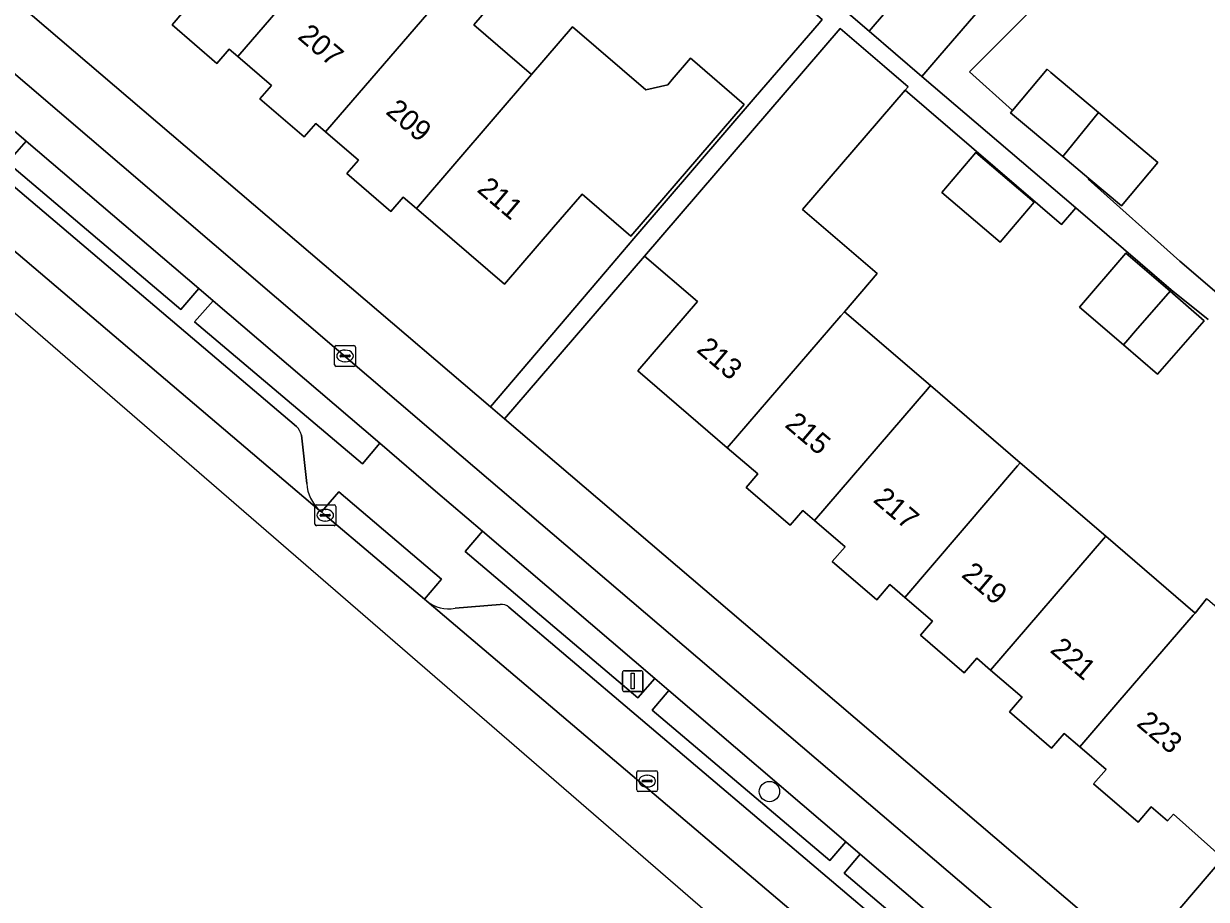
# Model space of a CAD drawing. Extents: x 162523 to 163266, y 381230 to 382050.
# Drawn here: x 162580.1 to 162636.9, y 381740.5 to 381782.6 of the extents above; entities that cross this region are included whole.
import ezdxf

# ---------------------------------------------------------------- set-up
doc = ezdxf.new("R2010")
doc.units = 0
for name, color, linetype in [('IMGEO_Berm_groen', 7, 'Continuous'), ('IMGEO_Berm_open', 7, 'Continuous'), ('IMGEO_Boom', 7, 'Continuous'), ('IMGEO_Brandkraan', 7, 'Continuous'), ('IMGEO_Erf', 7, 'Continuous'), ('IMGEO_Fietspad_gesloten', 7, 'Continuous'), ('IMGEO_Kolk', 7, 'Continuous'), ('IMGEO_Lichtmast', 7, 'Continuous'), ('IMGEO_Pand', 7, 'Continuous'), ('IMGEO_Pand_nummerreeks', 7, 'Continuous'), ('IMGEO_Parkeervlak_open', 7, 'Continuous'), ('IMGEO_Rijbaan_lokaal_gesloten', 7, 'Continuous'), ('IMGEO_Voetpad_open', 7, 'Continuous')]:
    doc.layers.add(name, color=color, linetype=linetype)

msp = doc.modelspace()

# ---------------------------------------------------------------- linework, layer by layer
at = {"layer": 'IMGEO_Berm_groen'}
for points in [[(162580.204, 381776.991), (162579.301, 381775.955), (162587.628, 381768.898), (162588.493, 381769.903)], [(162589.179, 381769.316), (162588.292, 381768.298), (162596.362, 381761.478), (162597.187, 381762.468)], [(162602.123, 381758.248), (162601.292, 381757.262), (162609.598, 381750.237), (162610.407, 381751.166)], [(162611.084, 381750.587), (162610.29, 381749.64), (162618.823, 381742.409), (162619.592, 381743.314)], [(162620.285, 381742.721), (162619.506, 381741.806), (162627.912, 381734.688), (162628.68, 381735.544)]]:
    msp.add_lwpolyline(points, close=True, dxfattribs=at)
at = {"layer": 'IMGEO_Berm_open'}
for points in [[(162572.745, 381780.619), (162593.185, 381763.279)], [(162627.912, 381734.688), (162619.506, 381741.806), (162620.285, 381742.721), (162619.592, 381743.314), (162618.823, 381742.409), (162610.29, 381749.64), (162611.084, 381750.587), (162610.407, 381751.166), (162609.598, 381750.237), (162601.292, 381757.262), (162602.123, 381758.248), (162599.877, 381760.168), (162597.187, 381762.468), (162596.362, 381761.478), (162588.292, 381768.298), (162589.179, 381769.316), (162588.493, 381769.903), (162587.628, 381768.898), (162579.301, 381775.955), (162580.204, 381776.991), (162579.513, 381777.583)], [(162593.426, 381762.861), (162593.683, 381760.532)], [(162594.297, 381759.242), (162594.384, 381759.168), (162595.221, 381760.134), (162600.155, 381755.935), (162599.342, 381754.973), (162599.458, 381754.875)], [(162600.809, 381754.538), (162602.985, 381754.717)], [(162603.395, 381754.59), (162624.819, 381736.42)]]:
    msp.add_lwpolyline(points, dxfattribs=at)
for centre, radius, start, end in [((162592.627, 381762.679), 0.819, 12.8339, 47.0977), ((162595.587, 381760.647), 1.907, 183.454, 227.452), ((162600.495, 381756.154), 1.646, 230.9738, 281.0135), ((162603.061, 381754.236), 0.487, 46.6334, 98.9453)]:
    msp.add_arc(centre, radius, start, end, dxfattribs=at)
at = {"layer": 'IMGEO_Boom'}
msp.add_circle((162615.919, 381745.727), 0.489, dxfattribs=at)
at = {"layer": 'IMGEO_Brandkraan'}
for p, q in [((162595.022, 381766.238), (162595.022, 381767.09)), ((162595.097, 381767.164), (162595.949, 381767.164)), ((162595.51, 381766.944), (162595.535, 381766.944)), ((162596.023, 381767.09), (162596.023, 381766.238)), ((162595.281, 381766.658), (162595.281, 381766.67)), ((162595.719, 381766.621), (162595.321, 381766.621)), ((162595.324, 381766.707), (162595.722, 381766.707)), ((162595.533, 381766.384), (162595.508, 381766.384)), ((162595.765, 381766.67), (162595.765, 381766.658)), ((162595.949, 381766.164), (162595.097, 381766.164))]:
    msp.add_line(p, q, dxfattribs=at)
for points in [[(162595.022, 381766.238), (162595.022, 381767.09)], [(162595.097, 381767.164), (162595.949, 381767.164)], [(162596.023, 381767.09), (162596.023, 381766.238)], [(162595.949, 381766.164), (162595.097, 381766.164)]]:
    msp.add_lwpolyline(points, dxfattribs=at)
for centre, radius, start, end in [((162595.099, 381767.088), 0.0765, 91.552, 178.448), ((162595.099, 381767.088), 0.0765, 91.552, 178.448), ((162595.947, 381767.088), 0.0765, 1.552, 88.448), ((162595.947, 381767.088), 0.0765, 1.552, 88.448), ((162595.099, 381766.24), 0.0765, 181.552, 268.448), ((162595.099, 381766.24), 0.0765, 181.552, 268.448), ((162595.321, 381766.667), 0.0403, 85.8775, 175.7526), ((162595.318, 381766.657), 0.0366, 178.938, 274.7102), ((162595.722, 381766.664), 0.043, 264.8664, 352.4533), ((162595.726, 381766.669), 0.0386, 1.7309, 96.639), ((162595.947, 381766.24), 0.0765, 271.552, 358.448), ((162595.947, 381766.24), 0.0765, 271.552, 358.448)]:
    msp.add_arc(centre, radius, start, end, dxfattribs=at)
for centre, major_axis, ratio, start_param, end_param in [((162595.509, 381766.664), (-0.387, 0.002), 0.722429, 4.712389, 7.853982), ((162595.534, 381766.664), (-0.39, 0.002), 0.717154, 1.570796, 4.712389)]:
    msp.add_ellipse(centre, major_axis=major_axis, ratio=ratio, start_param=start_param, end_param=end_param, dxfattribs=at)
at = {"layer": 'IMGEO_Erf'}
for points in [[(162549.054, 381809.864), (162602.511, 381764.218), (162608.044, 381770.714), (162609.399, 381772.305), (162615.239, 381779.1), (162618.303, 381782.666), (162618.448, 381782.836), (162612.38, 381788.011), (162610.349, 381789.742), (162611.057, 381790.567), (162610.568, 381790.987), (162608.033, 381793.165), (162605.498, 381795.343), (162602.964, 381797.522), (162600.429, 381799.7), (162597.894, 381801.878), (162595.359, 381804.056), (162592.824, 381806.234), (162590.289, 381808.413), (162588.022, 381810.361), (162584.229, 381805.946), (162580.559, 381801.594), (162578.078, 381803.689)], [(162603.937, 381785.179), (162601.706, 381782.58), (162604.485, 381780.192), (162606.452, 381782.481), (162609.976, 381779.451), (162611.034, 381779.701), (162611.251, 381779.954), (162612.126, 381780.973), (162612.218, 381780.894), (162614.705, 381778.757), (162609.262, 381772.423), (162606.912, 381774.443), (162605.543, 381772.85), (162603.19, 381770.112), (162598.952, 381773.754), (162598.317, 381774.3), (162597.722, 381773.608), (162595.606, 381775.427), (162596.163, 381776.075), (162594.587, 381777.43), (162594.114, 381777.836), (162593.561, 381777.193), (162591.426, 381779.027), (162591.98, 381779.671), (162590.368, 381781.056), (162589.951, 381781.415), (162589.36, 381780.727), (162587.209, 381782.576), (162587.78, 381783.24)], [(162628.845, 381783.631), (162625.54, 381780.326), (162627.603, 381778.469), (162629.26, 381780.442), (162629.439, 381780.292), (162631.729, 381778.368), (162634.592, 381775.963), (162632.84, 381773.877), (162631.275, 381775.192), (162631.242, 381775.155), (162635.646, 381771.227), (162638.212, 381769.032)], [(162636.996, 381768.418), (162635.231, 381769.841), (162630.643, 381773.79), (162629.953, 381772.98), (162622.441, 381779.445), (162617.514, 381773.709), (162621.101, 381770.629), (162619.522, 381768.791), (162623.657, 381765.237), (162627.976, 381761.526), (162632.08, 381758), (162636.378, 381754.306), (162636.928, 381754.989)]]:
    msp.add_lwpolyline(points, dxfattribs=at)
for points in [[(162624.198, 381774.516), (162625.84, 381776.446), (162628.643, 381774.06), (162627.001, 381772.13)], [(162623.171, 381753.249), (162623.75, 381753.923), (162622.427, 381755.06), (162621.709, 381755.677), (162621.077, 381754.942), (162618.936, 381756.782), (162619.55, 381757.497), (162618.078, 381758.762), (162617.524, 381759.238), (162616.913, 381758.528), (162614.803, 381760.341), (162615.361, 381760.991), (162613.893, 381762.252), (162609.593, 381765.948), (162612.46, 381769.285), (162609.92, 381771.468), (162603.191, 381763.638), (162619.163, 381750), (162633.579, 381737.69), (162637.705, 381742.522), (162635.34, 381744.646), (162635.056, 381744.315), (162634.271, 381744.989), (162633.638, 381744.253), (162631.499, 381746.091), (162632.097, 381746.787), (162630.831, 381747.876), (162630.088, 381748.514), (162629.481, 381747.808), (162627.451, 381749.552), (162627.836, 381750), (162628.062, 381750.263), (162626.545, 381751.566), (162625.886, 381752.133), (162625.285, 381751.432)], [(162632.928, 381767.201), (162630.821, 381769.012), (162633.047, 381771.601), (162635.173, 381769.774), (162636.819, 381768.359), (162634.575, 381765.786)]]:
    msp.add_lwpolyline(points, close=True, dxfattribs=at)
at = {"layer": 'IMGEO_Fietspad_gesloten'}
for points in [[(162601.096, 381761.857), (162549.056, 381806.402), (162548.287, 381807.068)], [(162546.004, 381806.321), (162547.12, 381805.283), (162565.997, 381789.141), (162571.272, 381784.63), (162579.513, 381777.583), (162580.204, 381776.991), (162588.493, 381769.903), (162589.179, 381769.316), (162597.187, 381762.468), (162599.877, 381760.168), (162602.123, 381758.248), (162610.407, 381751.166), (162611.084, 381750.587), (162619.592, 381743.314), (162620.285, 381742.721), (162628.68, 381735.544)], [(162634.563, 381733.29), (162601.096, 381761.857)]]:
    msp.add_lwpolyline(points, dxfattribs=at)
at = {"layer": 'IMGEO_Kolk'}
for p, q in [((162594.072, 381758.581), (162594.072, 381759.433)), ((162594.147, 381759.507), (162594.999, 381759.507)), ((162595.073, 381759.433), (162595.073, 381758.581)), ((162594.331, 381759.001), (162594.331, 381759.013)), ((162594.769, 381758.964), (162594.371, 381758.964)), ((162594.374, 381759.05), (162594.772, 381759.05)), ((162594.56, 381759.287), (162594.585, 381759.287)), ((162594.815, 381759.013), (162594.815, 381759.001)), ((162594.999, 381758.507), (162594.147, 381758.507)), ((162594.583, 381758.727), (162594.558, 381758.727)), ((162609.539, 381745.803), (162609.539, 381746.655)), ((162609.614, 381746.729), (162610.466, 381746.729)), ((162610.027, 381746.509), (162610.052, 381746.509)), ((162610.54, 381746.655), (162610.54, 381745.803)), ((162610.466, 381745.729), (162609.614, 381745.729)), ((162609.798, 381746.223), (162609.798, 381746.235)), ((162610.236, 381746.186), (162609.838, 381746.186)), ((162609.841, 381746.272), (162610.239, 381746.272)), ((162610.05, 381745.949), (162610.025, 381745.949)), ((162610.282, 381746.235), (162610.282, 381746.223))]:
    msp.add_line(p, q, dxfattribs=at)
for points in [[(162594.072, 381758.581), (162594.072, 381759.433)], [(162594.147, 381759.507), (162594.999, 381759.507)], [(162595.073, 381759.433), (162595.073, 381758.581)], [(162594.999, 381758.507), (162594.147, 381758.507)], [(162609.539, 381745.803), (162609.539, 381746.655)], [(162609.614, 381746.729), (162610.466, 381746.729)], [(162610.54, 381746.655), (162610.54, 381745.803)], [(162610.466, 381745.729), (162609.614, 381745.729)]]:
    msp.add_lwpolyline(points, dxfattribs=at)
for centre, radius, start, end in [((162594.149, 381759.431), 0.0765, 91.552, 178.448), ((162594.149, 381759.431), 0.0765, 91.552, 178.448), ((162594.997, 381759.431), 0.0765, 1.552, 88.448), ((162594.997, 381759.431), 0.0765, 1.552, 88.448), ((162594.371, 381759.01), 0.0403, 85.8775, 175.7526), ((162594.368, 381759), 0.0366, 178.938, 274.7102), ((162594.772, 381759.007), 0.043, 264.8664, 352.4533), ((162594.776, 381759.012), 0.0386, 1.7309, 96.639), ((162594.149, 381758.583), 0.0765, 181.552, 268.448), ((162594.149, 381758.583), 0.0765, 181.552, 268.448), ((162594.997, 381758.583), 0.0765, 271.552, 358.448), ((162594.997, 381758.583), 0.0765, 271.552, 358.448), ((162609.616, 381746.653), 0.0765, 91.552, 178.448), ((162609.616, 381746.653), 0.0765, 91.552, 178.448), ((162610.464, 381746.653), 0.0765, 1.552, 88.448), ((162610.464, 381746.653), 0.0765, 1.552, 88.448), ((162609.616, 381745.805), 0.0765, 181.552, 268.448), ((162609.616, 381745.805), 0.0765, 181.552, 268.448), ((162609.838, 381746.232), 0.0403, 85.8775, 175.7526), ((162609.835, 381746.222), 0.0366, 178.938, 274.7102), ((162610.239, 381746.229), 0.043, 264.8664, 352.4533), ((162610.243, 381746.234), 0.0386, 1.7309, 96.639), ((162610.464, 381745.805), 0.0765, 271.552, 358.448), ((162610.464, 381745.805), 0.0765, 271.552, 358.448)]:
    msp.add_arc(centre, radius, start, end, dxfattribs=at)
for centre, major_axis, ratio, start_param, end_param in [((162594.559, 381759.007), (-0.387, 0.002), 0.722429, 4.712389, 7.853982), ((162594.584, 381759.007), (-0.39, 0.002), 0.717154, 1.570796, 4.712389), ((162610.026, 381746.229), (-0.387, 0.002), 0.722429, 4.712389, 7.853982), ((162610.051, 381746.229), (-0.39, 0.002), 0.717154, 1.570796, 4.712389)]:
    msp.add_ellipse(centre, major_axis=major_axis, ratio=ratio, start_param=start_param, end_param=end_param, dxfattribs=at)
at = {"layer": 'IMGEO_Lichtmast'}
for p, q in [((162608.85, 381750.634), (162608.85, 381751.434)), ((162608.85, 381751.434), (162608.85, 381750.634)), ((162608.95, 381751.534), (162609.74, 381751.534)), ((162609.74, 381751.534), (162608.95, 381751.534)), ((162609.84, 381751.434), (162609.84, 381750.634)), ((162609.84, 381750.634), (162609.84, 381751.434)), ((162609.74, 381750.534), (162608.95, 381750.534)), ((162608.95, 381750.534), (162609.74, 381750.534))]:
    msp.add_line(p, q, dxfattribs=at)
msp.add_lwpolyline([(162609.27, 381751.409), (162609.42, 381751.409), (162609.42, 381750.659), (162609.27, 381750.659), (162609.27, 381751.409)], dxfattribs=at)
for centre, start, end in [((162608.95, 381751.434), 90, 180), ((162608.95, 381751.434), 90, 180), ((162609.74, 381751.434), 0, 90), ((162609.74, 381751.434), 360, 90), ((162608.95, 381750.634), 180, 270), ((162608.95, 381750.634), 180, 270), ((162609.74, 381750.634), 270, 0), ((162609.74, 381750.634), 270, 0)]:
    msp.add_arc(centre, 0.1, start, end, dxfattribs=at)
at = {"layer": 'IMGEO_Pand'}
for points in [[(162591.883, 381791.022), (162586.291, 381784.52), (162587.78, 381783.24), (162587.209, 381782.576), (162589.36, 381780.727), (162589.951, 381781.415), (162590.368, 381781.056), (162595.939, 381787.536)], [(162600.153, 381783.915), (162602.383, 381786.514), (162598.172, 381790.133), (162595.939, 381787.536), (162590.368, 381781.056), (162591.98, 381779.671), (162591.426, 381779.027), (162593.561, 381777.193), (162594.114, 381777.836), (162594.587, 381777.43)], [(162622.299, 381789.254), (162618.173, 381784.452), (162620.707, 381782.274), (162624.834, 381787.076)], [(162621.975, 381781.185), (162623.242, 381780.096), (162624.111, 381781.107), (162627.369, 381784.898), (162624.834, 381787.076), (162620.707, 381782.274)], [(162604.485, 381780.192), (162601.706, 381782.58), (162603.937, 381785.179), (162602.383, 381786.514), (162600.153, 381783.915), (162594.587, 381777.43), (162596.163, 381776.075), (162595.606, 381775.427), (162597.722, 381773.608), (162598.317, 381774.3), (162598.952, 381773.754)], [(162604.485, 381780.192), (162598.952, 381773.754), (162603.19, 381770.112), (162605.543, 381772.85), (162606.912, 381774.443), (162609.262, 381772.423), (162614.705, 381778.757), (162612.218, 381780.894), (162612.126, 381780.973), (162611.251, 381779.954), (162611.034, 381779.701), (162609.976, 381779.451), (162606.452, 381782.481)], [(162617.514, 381773.709), (162622.441, 381779.445), (162622.578, 381779.604), (162621.449, 381780.574), (162619.316, 381782.406), (162609.92, 381771.468), (162612.46, 381769.285), (162609.593, 381765.948), (162613.893, 381762.252), (162619.352, 381768.596), (162619.522, 381768.791), (162621.101, 381770.629)], [(162631.729, 381778.368), (162629.439, 381780.292), (162629.26, 381780.442), (162627.603, 381778.469), (162627.508, 381778.356), (162630.016, 381776.249)], [(162631.729, 381778.368), (162630.016, 381776.249), (162631.275, 381775.192), (162632.84, 381773.877), (162634.592, 381775.963)], [(162625.84, 381776.446), (162624.198, 381774.516), (162627.001, 381772.13), (162628.643, 381774.06)], [(162635.173, 381769.774), (162633.047, 381771.601), (162630.821, 381769.012), (162632.928, 381767.201), (162633.141, 381767.445), (162633.514, 381767.872)], [(162635.173, 381769.774), (162633.514, 381767.872), (162633.141, 381767.445), (162632.928, 381767.201), (162634.575, 381765.786), (162636.819, 381768.359)], [(162619.522, 381768.791), (162619.352, 381768.596), (162613.893, 381762.252), (162615.361, 381760.991), (162614.803, 381760.341), (162616.913, 381758.528), (162617.524, 381759.238), (162618.078, 381758.762), (162623.508, 381765.064), (162623.657, 381765.237)], [(162627.847, 381761.378), (162627.976, 381761.526), (162623.657, 381765.237), (162623.508, 381765.064), (162618.078, 381758.762), (162619.55, 381757.497), (162618.936, 381756.782), (162621.077, 381754.942), (162621.709, 381755.677), (162622.427, 381755.06)], [(162626.545, 381751.566), (162631.969, 381757.875), (162632.08, 381758), (162627.976, 381761.526), (162627.847, 381761.378), (162622.427, 381755.06), (162623.75, 381753.923), (162623.171, 381753.249), (162625.285, 381751.432), (162625.886, 381752.133)], [(162636.378, 381754.306), (162632.08, 381758), (162631.969, 381757.875), (162626.545, 381751.566), (162628.062, 381750.263), (162627.836, 381750), (162627.451, 381749.552), (162629.481, 381747.808), (162630.088, 381748.514), (162630.831, 381747.876), (162632.664, 381750), (162636.29, 381754.203)], [(162636.928, 381754.989), (162636.378, 381754.306), (162636.29, 381754.203), (162632.664, 381750), (162630.831, 381747.876), (162632.097, 381746.787), (162631.499, 381746.091), (162633.638, 381744.253), (162634.271, 381744.989), (162635.056, 381744.315), (162635.34, 381744.646), (162637.705, 381742.522), (162643.566, 381749.351), (162636.98, 381754.946)]]:
    msp.add_lwpolyline(points, close=True, dxfattribs=at)
at = {"layer": 'IMGEO_Parkeervlak_open'}
for points in [[(162568.532, 381781.143), (162594.297, 381759.242)], [(162593.185, 381763.279), (162572.745, 381780.619)], [(162593.683, 381760.532), (162593.426, 381762.861)], [(162599.458, 381754.875), (162625.869, 381732.446)], [(162602.985, 381754.717), (162600.809, 381754.538)], [(162624.819, 381736.42), (162603.395, 381754.59)]]:
    msp.add_lwpolyline(points, dxfattribs=at)
for centre, radius, start, end in [((162592.627, 381762.679), 0.819, 12.8339, 47.0977), ((162595.587, 381760.647), 1.907, 183.454, 227.452), ((162600.495, 381756.154), 1.646, 230.9738, 281.0135), ((162603.061, 381754.236), 0.487, 46.6334, 98.9453)]:
    msp.add_arc(centre, radius, start, end, dxfattribs=at)
at = {"layer": 'IMGEO_Rijbaan_lokaal_gesloten'}
for points in [[(162537.938, 381816.448), (162531.941, 381810.835), (162564.766, 381781.599), (162660.039, 381699.143), (162682.885, 381679.37)], [(162625.869, 381732.446), (162599.458, 381754.875), (162599.342, 381754.973), (162594.573, 381759.007), (162594.384, 381759.168), (162594.297, 381759.242), (162568.532, 381781.143), (162568.384, 381781.28), (162564.665, 381784.731), (162563.333, 381786.008), (162560.227, 381789.1), (162552.821, 381796.54), (162541.866, 381807.508), (162541.691, 381807.666)]]:
    msp.add_lwpolyline(points, dxfattribs=at)
at = {"layer": 'IMGEO_Voetpad_open'}
for points in [[(162693.781, 381686.286), (162665.388, 381710.53), (162664.663, 381711.149), (162634.463, 381736.935), (162633.579, 381737.69), (162619.163, 381750), (162603.191, 381763.638), (162602.511, 381764.218), (162549.054, 381809.864)], [(162548.287, 381807.068), (162549.056, 381806.402), (162601.096, 381761.857), (162634.563, 381733.29), (162680.601, 381693.932), (162686.514, 381688.902)], [(162638.212, 381769.032), (162635.646, 381771.227), (162631.242, 381775.155), (162631.275, 381775.192), (162630.016, 381776.249), (162627.508, 381778.356), (162627.603, 381778.469), (162625.54, 381780.326), (162628.845, 381783.631), (162627.369, 381784.898), (162624.111, 381781.107), (162623.242, 381780.096), (162630.643, 381773.79), (162635.231, 381769.841), (162636.996, 381768.418)], [(162637.705, 381742.522), (162633.579, 381737.69)]]:
    msp.add_lwpolyline(points, dxfattribs=at)
for points in [[(162619.316, 381782.406), (162621.449, 381780.574), (162622.578, 381779.604), (162622.441, 381779.445), (162629.953, 381772.98), (162630.643, 381773.79), (162623.242, 381780.096), (162621.975, 381781.185), (162620.707, 381782.274), (162618.173, 381784.452), (162615.638, 381786.63), (162613.103, 381788.809), (162611.057, 381790.567), (162610.349, 381789.742), (162612.38, 381788.011), (162618.448, 381782.836), (162618.303, 381782.666), (162615.239, 381779.1), (162609.399, 381772.305), (162608.044, 381770.714), (162602.511, 381764.218), (162603.191, 381763.638), (162609.92, 381771.468)], [(162594.384, 381759.168), (162594.573, 381759.007), (162599.342, 381754.973), (162600.155, 381755.935), (162595.221, 381760.134)]]:
    msp.add_lwpolyline(points, close=True, dxfattribs=at)

# ---------------------------------------------------------------- texts
at = {"layer": 'IMGEO_Pand_nummerreeks'}
for s, rotation, p in [('207', 319.5205, (162593.198, 381781.952)), ('209', 319.5205, (162597.43, 381778.34)), ('211', 319.5205, (162601.818, 381774.596)), ('213', 319.6466, (162612.366, 381766.898)), ('215', 319.6492, (162616.609, 381763.293)), ('217', 319.6466, (162620.853, 381759.687)), ('219', 319.6492, (162625.097, 381756.082)), ('221', 319.6492, (162629.357, 381752.462)), ('223', 319.6466, (162633.515, 381748.93))]:
    msp.add_text(s, height=1, rotation=rotation, dxfattribs=at).set_placement(p)

doc.saveas('drawing.dxf')
